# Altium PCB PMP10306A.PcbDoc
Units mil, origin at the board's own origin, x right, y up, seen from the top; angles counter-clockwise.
Board outline 4950 x 3450 mil, 2 copper layers (Top Layer, Bottom Layer), stack 62 mil thick; 21 components, 0 nets, 12 pads, 0 vias.
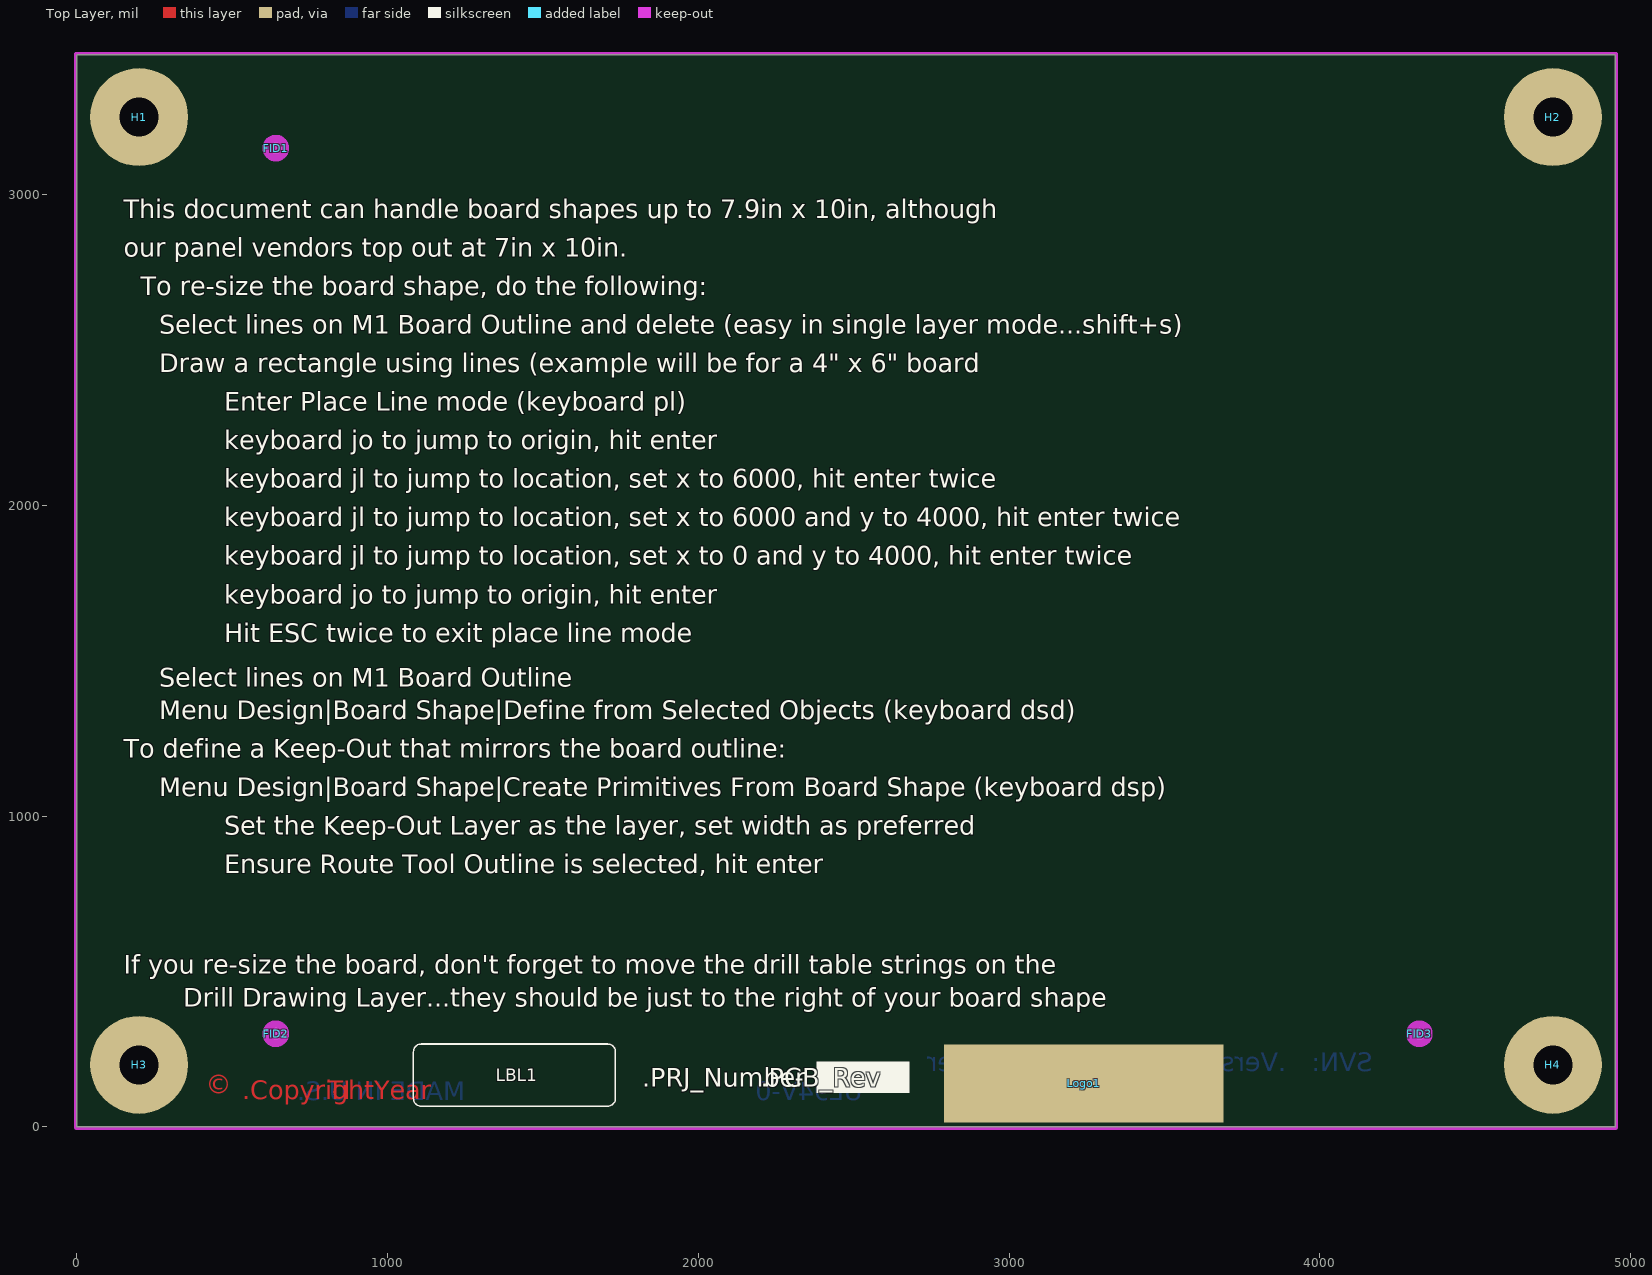
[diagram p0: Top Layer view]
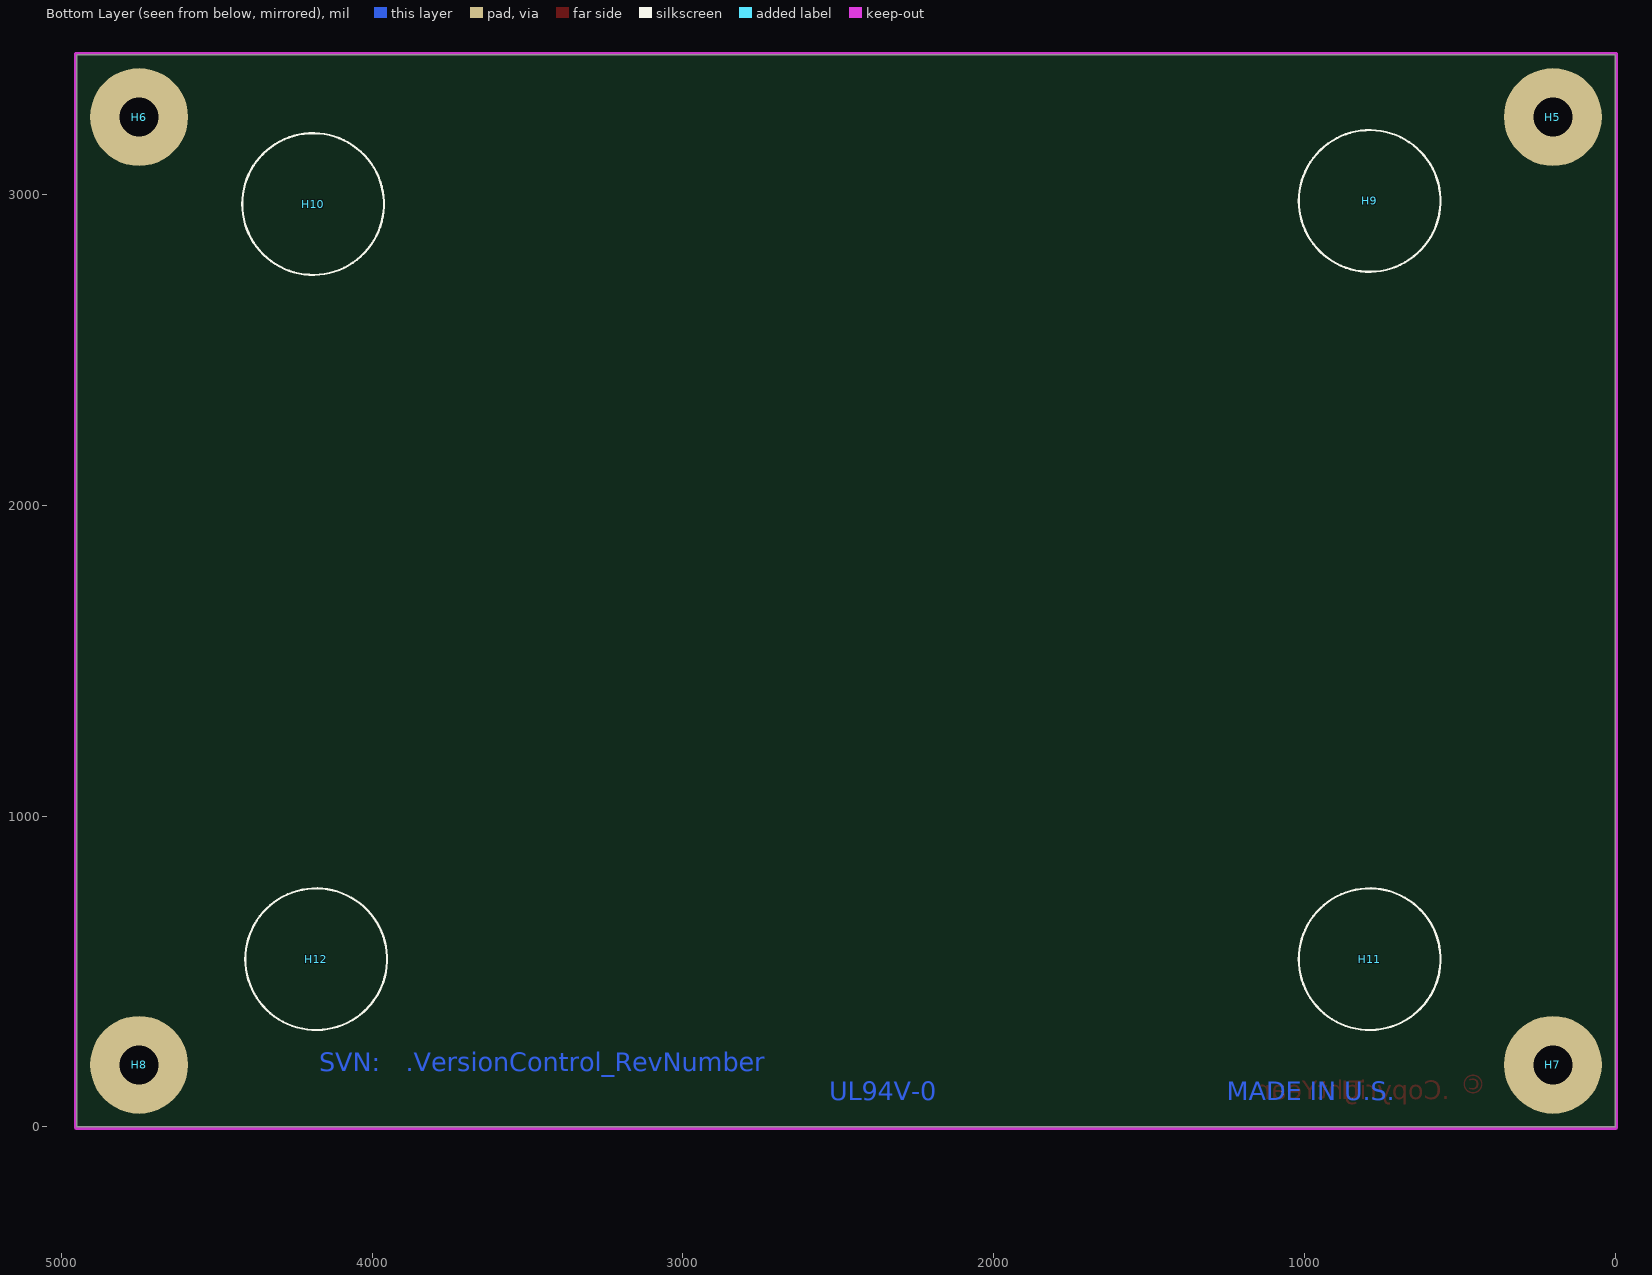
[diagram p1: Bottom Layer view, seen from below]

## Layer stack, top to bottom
Top Layer: signal copper 1.4
Dielectric: core 59.2, FR-4, Dk 4.8
Bottom Layer: signal copper 1.4

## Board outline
0,0 4950,0 4950,3450 0,3450

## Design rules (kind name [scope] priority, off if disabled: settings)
AcuteAngle [All] p1: minimum=4.50000000000000E+0001 checktracksonly=FALSE
AssemblyTestPointUsage [All] p1: valid=2
Clearance Clearance_BoardEdge_MountingHoles [OnCopper and InComponentClass('Mounting Holes') vs IsKeepOut] p1: gap=40
Clearance Clearance_BoardEdge_Poly [OnCopper and InPoly vs IsKeepOut] p2: gap=25
Clearance Clearance_BoardEdge [OnCopper and Not InComponentClass('Logo') and not InComponentClass('FiducialMark') and not InRegion(1000,500,4000,800) and Not IsKeepout vs IsKeepOut] p3: gap=75
Clearance Clearance_Poly [InPolygon] p4: gap=25
Clearance [All] p5: gap=8
ComponentClearance ComponentClearance_Shunt [InComponentClass('Header') vs InComponentClass('Shunt')] p1: gap=0 collisioncheckmode=3 verticalgap=0 showdistances=FALSE
ComponentClearance ComponentClearance_Logo [InComponentClass('Logo')] p2: gap=50 collisioncheckmode=3 verticalgap=10 showdistances=FALSE
ComponentClearance ComponentClearance_ScrewToNut [(HasFootprint('NY PMS 440 0025 PH')) vs (HasFootprint('Keystone_1902C'))] p3: gap=5 collisioncheckmode=3 verticalgap=10 showdistances=FALSE
ComponentClearance ComponentClearance_MountingHoles [InComponentClass('Mounting Holes')] p4: gap=250 collisioncheckmode=3 verticalgap=100000 showdistances=FALSE
ComponentClearance ComponentClearance_SmallPassives [HasFootprint('0201*') or HasFootprint('0402*') or HasFootprint('0508') or HasFootprint('0603*') or HasFootprint('0612') or HasFootprint('0805*') or HasFootprint('0815*') or HasFootprint('0830*') or HasFootprint('1206*') or HasFootprint('1210*') or HasFootprint('1808*') or HasFootprint('1812*') or HasFootprint('1825*') or HasFootprint('2010*') or HasFootprint('2220*') or HasFootprint('2225*') or HasFootprint('2512*') or HasFootprint('2728*') or HasFootprint('3518*') vs HasFootprint('0201*') or HasFootprint('0402*') or HasFootprint('0508') or HasFootprint('0603*') or HasFootprint('0612') or HasFootprint('0805*') or HasFootprint('0815*') or HasFootprint('0830*') or HasFootprint('1206*') or HasFootprint('1210*') or HasFootprint('1808*') or HasFootprint('1812*') or HasFootprint('1825*') or HasFootprint('2010*') or HasFootprint('2220*') or HasFootprint('2225*') or HasFootprint('2512*') or HasFootprint('2728*') or HasFootprint('3518*')] p5: gap=20 collisioncheckmode=3 verticalgap=10 showdistances=FALSE
ComponentClearance ComponentClearance_THtoSMT [IsThruComponent vs IsSMTComponent] p6: gap=100 collisioncheckmode=3 verticalgap=30 showdistances=FALSE
ComponentClearance ComponentClearance_THtoTH [IsThruComponent vs IsThruComponent] p7: gap=118.11 collisioncheckmode=3 verticalgap=30 showdistances=FALSE
ComponentClearance [All] p8: gap=40 collisioncheckmode=3 verticalgap=10 showdistances=FALSE
DiffPairsRouting [All] p1: maxlimit=100 minlimit=10 mostfreqgap=10 maxuncoupledlength=1000
FabricationTestPointUsage TestPointUsage [All] p1: valid=2 allowmultiple=FALSE
FabricationTestpoint Testpoint [All] p1: side=3 testpointundercomponent=TRUE minsize=40 maxsize=100 preferedsize=60 minholesize=0 maxholesize=40 preferedholesize=32 testpointgrid=1 allowsidetop=TRUE allowsidebottom=TRUE usegrid=TRUE gridtolerance=0.01
FanoutControl Fanout_LCC [IsLCC] p1: bgadir=Out bgaviamode=Centered fanoutstyle=Auto fanoutdirection=Alternating viagrid=1 // Fanout_LCC (Default Rule)
FanoutControl Fanout_BGA [IsBGA] p2: bgadir=Out bgaviamode=Centered fanoutstyle=Auto fanoutdirection=Alternating viagrid=1 // Fanout_BGA (Default Rule)
FanoutControl Fanout_Default [All] p4: bgadir=Out bgaviamode=Centered fanoutstyle=Auto fanoutdirection=Alternating viagrid=1 // Fanout_Default (Default Rule)
FanoutControl Fanout_Small [(CompPinCount < 5)] p5: bgadir=Out bgaviamode=Centered fanoutstyle=Auto fanoutdirection=OutThenIn viagrid=1 // Fanout_Small (Default Rule)
HoleSize [All] p1: absolutevalues=TRUE maxlimit=251 minlimit=8 maxpercent=80.000 minpercent=20.000
MinimumAnnularRing MinimumAnnularRing_ThermalPadVias [IsVia and InAnyComponent] p1: minimumring=5.91
MinimumAnnularRing [All] p2: minimumring=9
MinimumSolderMaskSliver MinimumSolderMaskSliver_Logo [InComponentClass('Logo') vs InComponentClass('Logo')] p1: minsoldermaskwidth=0.7
MinimumSolderMaskSliver [All] p2: minsoldermaskwidth=3.94
PlaneConnect [All] p1: planeconnectstyle=Relief reliefexpansion=10 reliefentries=4 reliefconductorwidth=10 reliefairgap=10
PolygonConnect [All] p1: connectstyle=Relief reliefconductorwidth=10 reliefentries=4 polygonreliefangle="90 Angle" airgapwidth=10
RoutingVias ThermalPadVias [IsVia and InAnyComponent] p1: holewidth=7.87 width=19.68 viastyle="Through Hole" minholewidth=7.87 minwidth=19.68 maxholewidth=12.99 maxwidth=23.62
RoutingVias [All] p2: holewidth=16 width=34 viastyle="Through Hole" minholewidth=7.87 minwidth=26 maxholewidth=40 maxwidth=65
SMDToCorner [All] p1: distance=30000
SilkToSilkClearance [All] p1: silktosilkclearance=5
SilkscreenOverComponentPads [All] p1: minsilkscreentomaskgap=5
SolderMaskExpansion [All] p1: expansion=1.97
Width [All] p1: maxlimit=100 minlimit=6 preferedwidth=10 checkconnectedcopper=TRUE
14 further rules are at their usual default settings.

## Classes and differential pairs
component class "Mounting Holes": H1 H2 H3 H4
component class Logo: Logo1
component class FiducialMark: FID1 FID2 FID3
component class AssemblyNote: ZZ1 ZZ2 ZZ3 ZZ4
component class Label: LBL1

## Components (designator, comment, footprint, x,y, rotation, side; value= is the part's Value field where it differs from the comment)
FID1 "Fiducial" Fiducial10-20 640,3150 r0 top
FID2 "Fiducial" Fiducial10-20 640,300 r0 top
FID3 "Fiducial" Fiducial10-20 4320,300 r0 top
H1 "NY PMS 440 0025 PH" "NY PMS 440 0025 PH" 200,3250 r0 top locked
H2 "NY PMS 440 0025 PH" "NY PMS 440 0025 PH" 4750,3250 r0 top locked
H3 "NY PMS 440 0025 PH" "NY PMS 440 0025 PH" 200,200 r0 top locked
H4 "NY PMS 440 0025 PH" "NY PMS 440 0025 PH" 4750,200 r0 top locked
H5 "1902C" Keystone_1902C 200,3250 r180 bottom locked
H6 "1902C" Keystone_1902C 4750,3250 r180 bottom locked
H7 "1902C" Keystone_1902C 200,200 r180 bottom locked
H8 "1902C" Keystone_1902C 4750,200 r180 bottom locked
H9 "SJ-5303 (CLEAR)" Bumpon_SJ5003Transparent 790,2980 r180 bottom
H10 "SJ-5303 (CLEAR)" Bumpon_SJ5003Transparent 4190,2970 r180 bottom
H11 "SJ-5303 (CLEAR)" Bumpon_SJ5003Transparent 790,540 r180 bottom
H12 "SJ-5303 (CLEAR)" Bumpon_SJ5003Transparent 4180,540 r180 bottom
LBL1 "Size: 0.65\" x 0.20 \"" Label_650x200 1408,167 r0 top
Logo1 "Texas Instruments" TI_Stacked_SolderMask_Small 3240,140 r0 top
ZZ1 "This Assembly Note is for PCB labels only" AssemblyNoteLabel 185,3938 r0 top
ZZ2 "These assemblies are ESD sensitive, ESD precautions shall be observed." AssemblyNote 185,3829.11 r0 top
ZZ3 "These assemblies must be clean and free from flux and all contaminants. Use of no clean flux is not acceptable." AssemblyNote 185,3740.56 r0 top
ZZ4 "These assemblies must comply with workmanship standards IPC-A-610 Class 2, unless otherwise specified." AssemblyNote 185,3652 r0 top

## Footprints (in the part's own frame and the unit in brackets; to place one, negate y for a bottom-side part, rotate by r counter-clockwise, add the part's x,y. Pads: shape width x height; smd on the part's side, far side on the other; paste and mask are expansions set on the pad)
AssemblyNote [mil] "Assembly Note"
AssemblyNoteLabel [mil] "Assembly Note for PCB Labels"
Bumpon_SJ5003Transparent [mil] "3M Hemispherical Bumpon transparent"
  round 1 on Mech4: 0(0,0)
  silkscreen extent -228,-228 228,228, body extent -217,-218 219,218, height 197
Fiducial10-20 [mm]
  round 1 smd paste-0.5 mask+0.5: 1(0,0)
  Top Layer keep-out circle w1.178: c0,0 r0.5
Keystone_1902C [mil] "Hex Standoff, 4-40 threaded, nylon"
  body extent -145,-126 146,126, height 501
Label_650x200 [mil] "Thermal Transfer Label"
  silkscreen extent -325,-100 325,100, body extent -326,-101 326,101, height 1
"NY PMS 440 0025 PH" [mm] "4-40 nylon screw and mounting hole"
  round 8 hole 3.2: 1(0,0)
  body extent -3.3,-3.3 3.3,3.3, height 2.69
TI_Stacked_SolderMask_Small [mil]
  rect 900x250 smd paste-125 mask-125: 0(0,0)

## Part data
FID1 FID2 FID3: "Fiducial mark.  There is nothing to buy or mount."
H1 H2 H3 H4: "Machine Screw, Round, #4-40 x 1/4, Nylon, Philips panhead"
H5 H6 H7 H8: "Standoff, Hex, 0.5\"L #4-40 Nylon"
H9 H10 H11 H12: "Bumpon, Hemisphere, 0.44 X 0.20, Clear"
LBL1: library part THT-14-423-10, "Thermal Transfer Printable Labels, 0.650\" W x 0.200\" H - 10,000 per roll"
Logo1: library part TI_Logo, "Texas Instrument Corporate Signature"
ZZ1: library part AssemblyNoteLabel
ZZ2 ZZ3 ZZ4: library part AssemblyNote

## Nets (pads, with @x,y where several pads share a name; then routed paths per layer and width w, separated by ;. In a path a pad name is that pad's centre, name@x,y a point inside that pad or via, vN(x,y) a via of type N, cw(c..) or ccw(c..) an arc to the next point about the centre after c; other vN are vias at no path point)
pads on no net: FID1.1 FID2.1 FID3.1 H1.1 H2.1 H3.1 H4.1 H9.0 H10.0 H11.0 H12.0 Logo1.0

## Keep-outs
Keep-Out Layer:
  lines w10: -5,0 ccw(c0,0) 0,-5 ; -5,0 ccw(c0,0) 0,-5 ; -5,0 ccw(c0,0) 0,-5 ; -5,0 ccw(c0,0) 0,-5 ; -5,0 ccw(c0,0) 0,-5 ; -5,0 ccw(c0,0) 0,-5 ; -5,0 -5,3450 ; -5,3450 cw(c0,3450) 0,3455 ; -5,3450 cw(c0,3450) 0,3455 ; -5,3450 cw(c0,3450) 0,3455 ; -5,3450 cw(c0,3450) 0,3455 ; -5,3450 cw(c0,3450) 0,3455 ; -5,3450 cw(c0,3450) 0,3455 ; 0,-5 4950,-5 ; 0,3455 4950,3455 ; 4950,-5 ccw(c4950,0) 4955,0 ; 4950,-5 ccw(c4950,0) 4955,0 ; 4950,-5 ccw(c4950,0) 4955,0 ; 4950,-5 ccw(c4950,0) 4955,0 ; 4950,-5 ccw(c4950,0) 4955,0 ; 4950,-5 ccw(c4950,0) 4955,0 ; 4950,3455 cw(c4950,3450) 4955,3450 ; 4950,3455 cw(c4950,3450) 4955,3450 ; 4950,3455 cw(c4950,3450) 4955,3450 ; 4950,3455 cw(c4950,3450) 4955,3450 ; 4950,3455 cw(c4950,3450) 4955,3450 ; 4950,3455 cw(c4950,3450) 4955,3450 ; 4955,0 4955,3450
  text ".Layer_Name" at 577,-858.49 h60

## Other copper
Top Layer:
  text ".CopyrightYear" at 532,90 h60
  text "TI" at 808,90 h60
  text "©" at 415,86.48 h105
  text ".Layer_Name" at 577,-858.49 h60
Bottom Layer:
  text ".VersionControl_RevNumber" at 3891,179.5 h60
  text "SVN:" at 4170,179.5 h60
  text "MADE IN U.S." at 1250,86.5 h60
  text "UL94V-0" at 2529.5,86.5 h60
  text ".Layer_Name" at 577,-858.49 h60

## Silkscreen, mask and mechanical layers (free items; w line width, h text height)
Top Overlay:
  region: 2680,210 2380,210 2380,110 2680,110
  text "This document can handle board shapes up to 7.9in x 10in, although" at 150,2925 h60
  text "our panel vendors top out at 7in x 10in." at 150,2800.94 h60
  text "To re-size the board shape, do the following:" at 205,2676.88 h60
  text "Select lines on M1 Board Outline and delete (easy in single layer mode...shift+s)" at 265,2552.82 h60
  text "Draw a rectangle using lines (example will be for a 4\" x 6\" board" at 265,2428.76 h60
  text "Enter Place Line mode (keyboard pl)" at 475,2304.71 h60
  text "keyboard jo to jump to origin, hit enter" at 475,2180.65 h60
  text "keyboard jl to jump to location, set x to 6000, hit enter twice" at 475,2056.59 h60
  text "keyboard jl to jump to location, set x to 6000 and y to 4000, hit enter twice" at 475,1932.53 h60
  text "keyboard jl to jump to location, set x to 0 and y to 4000, hit enter twice" at 475,1808.47 h60
  text "keyboard jo to jump to origin, hit enter" at 475,1684.41 h60
  text "Hit ESC twice to exit place line mode" at 475,1560.35 h60
  text "Select lines on M1 Board Outline" at 265,1416.3 h60
  text "Menu Design|Board Shape|Define from Selected Objects (keyboard dsd)" at 265,1312.24 h60
  text "To define a Keep-Out that mirrors the board outline:" at 150,1188.18 h60
  text "Menu Design|Board Shape|Create Primitives From Board Shape (keyboard dsp)" at 265,1064.12 h60
  text "Set the Keep-Out Layer as the layer, set width as preferred" at 475,940.06 h60
  text "Ensure Route Tool Outline is selected, hit enter" at 475,816 h60
  text "If you re-size the board, don't forget to move the drill table strings on the" at 150,493 h60
  text "Drill Drawing Layer...they should be just to the right of your board shape" at 343,387 h60
  text ".PRJ_Number" at 1820,130.01 h60
  text ".PCB_Rev" at 2200,130.01 h60
  text "-" at 2310,130.01 h60
  text ".Layer_Name" at 577,-858.49 h60
Bottom Overlay:
  text ".Layer_Name" at 577,-858.49 h60
Top Paste:
  text ".Layer_Name" at 577,-858.49 h60
Bottom Paste:
  text ".Layer_Name" at 577,-858.49 h60
Top Solder:
  text ".Layer_Name" at 577,-858.49 h60
  text ".Layer_Name" at 577,-858.49 h60
Bottom Solder:
  text ".Layer_Name" at 577,-858.49 h60
Drill Guide:
  text ".Layer_Name" at 577,-858.49 h60
M1 Board Outline:
  the board outline again, w10
  text ".Layer_Name" at 577,-858.49 h60
M2 Board Dimensions:
  rectangle: -0.5,-285.5 124.5,-160.5
  rectangle: 124.5,-410.5 499.5,-285.5
  lines w7: -0.5,-285.5 999.5,-285.5 ; 124.5,-410.5 124.5,-160.5 ; 249.5,-410.5 249.5,-160.5 ; 499.5,-410.5 499.5,-160.5 ; 749.5,-410.5 749.5,-160.5 ; -0.5,-410.5 999.5,-410.5 999.5,-160.5 -0.5,-160.5 -0.5,-410.5
  lines w10: -0.5,-475.5 -0.5,-455.5 ; 59.5,-485.5 -0.5,-465.5 ; 59.5,-445.5 -0.5,-465.5 ; 223.58,-465.5 -0.5,-465.5 ; 775.42,-465.5 999.5,-465.5 ; 939.5,-485.5 999.5,-465.5 ; 939.5,-445.5 999.5,-465.5 ; 999.5,-475.5 999.5,-455.5
  text "1000 (mil)" at 233.58,-501.49 h60
  text ".Layer_Name" at 577,-858.49 h60
M3 3D STEP Top:
  text ".Layer_Name" at 577,-858.49 h60
M4 3D STEP Bottom:
  text ".Layer_Name" at 577,-858.49 h60
M5 Assembly Top:
  lines w10: -292,-930.17 6308,-930.17 ; -292,-726.83 6310,-726.83 ; -292,-523.5 -292,-1133.5 3713,-1133.5 6310,-1133.5 6310,-523.5 -291.5,-523.5 -291.5,-1133.5 1284,-1133.5 ; 2173,-1133.5 2173,-523.5 ; 3440,-726.83 3440,-523.5 ; 4280,-726.83 4280,-523.5 ; 4902,-1140 4902,-937.17
  text "COMPONENTS MARKED 'DNP' SHOULD NOT BE POPULATED." at 1153.5,-318.5 h60
  text "ASSEMBLY VARIANT:" at 1153,-434 h60
  text ".VariantName" at 2189,-434 h60
  text "PCB VIEWED FROM TOP SIDE" at -228.5,-655.67 h60
  text "BOARD #:" at 2248,-655.67 h60
  text ".PRJ_Number" at 2793.5,-655.67 h60
  text "REV:" at 3638,-655.67 h60
  text ".PCB_Rev" at 3929.5,-655.67 h60
  text "SVN REV:" at 4476,-655.67 h60
  text ".VersionControl_RevNumber" at 4982,-655.67 h60
  text "IGNORE ->" at -228.5,-858.49 h60
  text "PLOT NAME =" at -228.5,-1064.34 h60
  text ".plot_File_Name" at 577,-1064.34 h60
  text "GENERATED    :" at 2250,-1064.34 h60
  text ".Print_Date" at 3119.5,-1064.34 h60
  text ".Print_Time" at 3848.5,-1064.34 h60
  text "TEXAS INSTRUMENTS" at 5113,-1064.34 h60
M6 Assembly Bottom:
  lines w10: -292.5,-727.33 6309.5,-727.33 ; -290.5,-930.67 6309.5,-930.67 ; 1115.5,-1140.5 1115.5,-937.67 ; 1737.5,-727.33 1737.5,-524 ; 2577.5,-727.33 2577.5,-524 ; 3844.5,-1134 3844.5,-524 ; 4733.5,-1134 6309,-1134 6309,-524 -292.5,-524 -292.5,-1134 2304.5,-1134 6309.5,-1134 6309.5,-524
  text "COMPONENTS MARKED 'DNP' SHOULD NOT BE POPULATED." at 6102,-318 h60
  text ".VariantName" at 5058,-434 h60
  text "ASSEMBLY VARIANT:" at 6097,-434 h60
  text ".VersionControl_RevNumber" at 1035.5,-656.17 h60
  text "SVN REV:" at 1541.5,-656.17 h60
  text ".PCB_Rev" at 2088,-656.17 h60
  text "REV:" at 2379.5,-656.17 h60
  text ".PRJ_Number" at 3224,-656.17 h60
  text "BOARD #:" at 3769.5,-656.17 h60
  text "PCB VIEWED FROM BOTTOM SIDE" at 6246,-656.17 h60
  text "IGNORE ->" at 2547.85,-858.49 h60
  text "TEXAS INSTRUMENTS" at 904.5,-1064.84 h60
  text ".Print_Time" at 2169,-1064.84 h60
  text ".Print_Date" at 2898,-1064.84 h60
  text "GENERATED    :" at 3767.5,-1064.84 h60
  text ".plot_File_Name" at 5440.5,-1064.84 h60
  text "PLOT NAME =" at 6246,-1064.84 h60
M9 Title Sheet:
  drawing of 57 lines, arcs and shapes, not listed
  text "1" at 739.84,8036.5 h70
  text "2" at 3235.5,8036.5 h70
  text "3" at 5724.84,8036.5 h70
  text "4" at 8231.51,8036.5 h70
  text "5" at 10730.5,8036.5 h70
  text "6" at 13235.5,8036.5 h70
  text "A" at -416.5,6893.5 h70
  text "A" at 14383.5,6893.5 h70
  text "B" at -416.5,4513.5 h70
  text "B" at 14383.5,4513.5 h70
  text "C" at -416.5,2138.5 h70
  text "C" at 14383.5,2138.5 h70
  text "PROJECT TITLE:" at 11343.5,277.5 h45
  text ".PRJ_Title" at 11393.5,144.17 h70
  text "DESIGNED FOR:" at 11343.5,-23.5 h45
  text ".PRJ_Customer" at 11393.5,-163.5 h70
  text "D" at -416.5,-231.5 h70
  text "D" at 14383.5,-231.5 h70
  text "FILE NAME:" at 11343.5,-323.5 h45
  text ".PCB_File_Name_No_Path" at 11393.5,-443.5 h70
  text "Texas Instruments (TI) and/or its licensors do not warrant the accuracy or completeness of this specification" at 6374,-605.34 h45
  text "ENGINEER:" at 11343.5,-613.5 h45
  text "LAYOUT BY:" at 12848.5,-613.5 h45
  text "or any information contained therein. TI and/or its licensors do not warrant that this design will meet" at 6329.01,-718 h45
  text ".PRJ_Engineer" at 11393.5,-768.49 h70
  text ".PCB_Layout" at 12899,-768.49 h70
  text "the specifications, will be suitable for your application or fit for any particular purpose, or will operate in" at 6329.01,-830.67 h45
  text ".Layer_Name" at 577,-858.49 h60
  text "ALTIUM DESIGNER VERSION:" at 12848.5,-923.5 h45
  text "an implementation. TI and/or its licensors do not warrant that the design is production worthy. You should" at 6329.01,-943.33 h45
  text "completely validate and test your design implementation to confirm the system functionality for your application." at 6374,-1056 h45
  text ".print_Scale" at 11393.5,-1056.83 h70
  text ".Application_BuildNumber" at 12899,-1056.83 h70
  text "1" at 739.84,-1263.5 h70
  text "2" at 3235.5,-1263.5 h70
  text "3" at 5724.84,-1263.5 h70
  text "4" at 8231.51,-1263.5 h70
  text "5" at 10730.5,-1263.5 h70
  text "6" at 13235.5,-1263.5 h70
M10 Fab Notes:
  drawing of 212 lines, arcs and shapes, not listed
  text "DESIGN INFORMATION" at 12381.02,6810 h60
  text "(REFER ALSO ARRAY/PANEL PROFILING INFORMATION)" at 12019.46,6648.29 h60
  text "BOARD SIZE" at 11333.46,6644 h60
  text "3450MIL" at 11795.78,6516.18 h60
  text "X" at 12301.46,6516.18 h60
  text "4950MIL" at 12532.78,6516.18 h60
  text "Number of Layers :" at 11736.46,6319 h60
  text "2" at 12831.27,6309 h60
  text "MIN. TRACK WIDTH:" at 11736.46,6180 h60
  text "8" at 12832.7,6180 h60
  text "MIL" at 12987.46,6180 h60
  text "MIN. CLEARANCE:" at 11736.46,6048 h60
  text "8" at 12832.7,6048 h60
  text "MIL" at 12987.46,6048 h60
  text "MIN. VIA PAD SIZE:" at 11736.46,5916 h60
  text "24" at 12802.71,5916 h60
  text "MIL" at 12987.46,5916 h60
  text "0.05mm (2MIL)" at 12431.46,5774.29 h60
  text "MINIMUM ANNULAR RING" at 11407.23,5770 h60
  text "EXTERNAL" at 13139.46,5770 h60
  text "PER" at 11607.23,5652 h60
  text "IPC-D-275 CLASS 2 LEVEL C" at 11827.23,5652 h60
  text "MIL, HOLES" at 13315.46,5539.71 h60
  text "+/-" at 12923,5539 h60
  text "+/-" at 13777,5539 h60
  text "REGISTRATION TOLERANCES:" at 11407.23,5534 h60
  text "METAL" at 12607,5534 h60
  text "5" at 13183.2,5534 h60
  text "3" at 14016.2,5534 h60
  text "MIL" at 14132.46,5534 h60
  text "MATERIAL:" at 11332.46,5324.54 h60
  text "FR-4 High Tg" at 12318.9,5184.21 h60
  text "FR-408" at 11753.46,5175.64 h60
  text "X" at 12165.46,5175.64 h60
  text "OTHER" at 13241.46,5175.64 h60
  text "62 MIL (1.6mm) +/-10%" at 12073.56,5012.92 h60
  text "THICKNESS:" at 11407.23,5008.64 h60
  text "X" at 11945.4,5008.64 h60
  text "OTHER" at 13358.46,5008.64 h60
  text "TOLERANCE:" at 11407.23,4850.64 h60
  text "X" at 12246.53,4850.64 h60
  text "ANSI IPC-6012 TYPE 3 CLASS 2" at 12433.48,4850.64 h60
  text "OTHER +/-" at 12433.46,4694.64 h60
  text "BOW & TWIST:" at 11407.23,4537.64 h60
  text "X" at 12246.53,4537.64 h60
  text "ANSI IPC-6012 TYPE 3 CLASS 2" at 12433.48,4537.64 h60
  text "OTHER +/-" at 12433.46,4379.13 h60
  text "COPPER THICKNESS (FINISHED):" at 11332.46,4243.64 h60
  text "1.4MIL (1oz)" at 12212.46,4090.92 h60
  text "2MIL (1.4oz)" at 12979.46,4090.92 h60
  text "2.8MIL (2oz)" at 13706.46,4090.92 h60
  text "OUTER:" at 11689.46,4086.64 h60
  text "X" at 12084,4086 h60
  text "1.4MIL (1oz)" at 12212.46,3933.92 h60
  text "2.8MIL (2oz)" at 12979.46,3933.92 h60
  text "N/A" at 13706,3934.29 h60
  text "INNER SIGNAL:" at 11400.38,3929.64 h60
  text "X" at 12085.42,3929.64 h60
  text "DRILLING:" at 11332.46,3790.64 h60
  text "REFERENCE:" at 11407.23,3673.64 h60
  text "X" at 12055.46,3673.64 h60
  text "AS SHOWN" at 12242.46,3673.64 h60
  text "X" at 12956.46,3673.64 h60
  text "NC_DRILL FILES" at 13093.46,3673.64 h60
  text "PTH MIN COPPER THICKNESS:" at 11407.23,3515.64 h60
  text "X" at 12757.46,3515.64 h60
  text "1MIL" at 12894.46,3515.64 h60
  text "OTHER" at 13391.46,3515.64 h60
  text "BOARD FINISH:" at 11332.46,3356.64 h60
  text "SILKSCREEN:" at 11487.68,3238.64 h60
  text "X" at 12436.46,3238.64 h60
  text "TOP" at 12562.46,3238.64 h60
  text "X" at 12946.46,3238.64 h60
  text "BOTTOM" at 13073.46,3238.64 h60
  text "SILKSCREEN COLOR:" at 11487.68,3071.64 h60
  text "X" at 12435.42,3071.64 h60
  text "WHITE" at 12562.46,3071.64 h60
  text "OTHER" at 13073.46,3071.64 h60
  text "SOLDER RESIST COLOR:" at 11487.68,2901.64 h60
  text "X" at 12055.42,2742.44 h60
  text "GREEN" at 12182.46,2742.44 h60
  text "BLUE" at 12773.46,2742.44 h60
  text "OTHER" at 13311.46,2742.44 h60
  text "IMMERSION GOLD (ENIG)" at 12393.46,2553.92 h60
  text "ENEPIG" at 13731,2550.64 h60
  text "SURFACE FINISH:" at 11332.46,2549.64 h60
  text "X" at 12206.51,2549.64 h60
  text "IMM. TIN/SILVER OR EQUIV" at 11662,2392.64 h60
  text "OTHER" at 13093.46,2392.64 h60
  text "ARRAY/PANEL:" at 11332.46,2213.64 h60
  text "CUT AND TRIM PER MECH LAYER 1" at 12393.46,2209.35 h60
  text "N.C. ROUTE" at 12393.46,2057.64 h60
  text "X" at 13072.46,2057.64 h60
  text "V. SCORE" at 13259.46,2057.64 h60
  text "CERTIFICATION:" at 11332.46,1920.64 h60
  text "MATERIALS AND WORKMANSHIP FOR ALL PCBS" at 12057.46,1920.64 h60
  text "TO MEET OR EXCEED THE REQUIREMENTS OF:" at 12057.46,1822.64 h60
  text "X" at 11683.96,1686.13 h60
  text "ANSI IPC-A-600F CLASS ->" at 11822.96,1686.13 h60
  text "X" at 13462.02,1686.13 h60
  text "2" at 13580.96,1686.14 h60
  text "1" at 13265.96,1684.64 h60
  text "3" at 13934.96,1684.64 h60
  text "X" at 11686.02,1526.64 h60
  text "UL 94V-0" at 11822.96,1526.64 h60
  text "X" at 12498.02,1526.64 h60
  text "RoHS" at 12634.96,1526.64 h60
  text "OTHER" at 13279.36,1526.64 h60
  text "PER ORDER" at 13676.42,1526.64 h60
  text "ADDITIONAL REQUIREMENTS:" at 11332.46,1385.64 h60
  text "MICROSECTION:" at 11407.23,1270.64 h60
  text "YES" at 12312.96,1270.64 h60
  text "REQUIRED" at 13174.46,1114.49 h60
  text "BARE BOARD ELEC. TEST:" at 11407.23,1111.64 h60
  text "NONE" at 12712.96,1111.64 h60
  text "X" at 13047.46,1111.64 h60
  text "PER ORDER" at 13766.46,1111.64 h60
  text "MANUFACTURER'S UL:" at 11407.23,954.64 h60
  text "RAIL" at 12572.96,950.35 h60
  text "METAL" at 13064.77,950.35 h60
  text "X" at 13440,950 h60
  text "SILK" at 13576.46,950.35 h60
  text ".Layer_Name" at 577,-858.49 h60
M11 Gerber Information:
  lines w10: -292,-930.17 6308,-930.17 ; -292,-726.83 6310,-726.83 ; -292,-523.5 -292,-1133.5 3713,-1133.5 6310,-1133.5 6310,-523.5 -291.5,-523.5 -291.5,-1133.5 1284,-1133.5 ; 2173,-1133.5 2173,-523.5 ; 3440,-726.83 3440,-523.5 ; 4280,-726.83 4280,-523.5 ; 4902,-1140 4902,-937.17
  text "ALL ARTWORK VIEWED FROM TOP SIDE" at -228.5,-655.67 h60
  text "BOARD #:" at 2248,-655.67 h60
  text ".PRJ_Number" at 2793.5,-655.67 h60
  text "REV:" at 3638,-655.67 h60
  text ".PCB_Rev" at 3929.5,-655.67 h60
  text "SVN REV:" at 4476,-655.67 h60
  text ".VersionControl_RevNumber" at 4982,-655.67 h60
  text "LAYER NAME =" at -228.5,-858.49 h60
  text "PLOT NAME =" at -228.5,-1064.34 h60
  text ".plot_File_Name" at 577,-1064.34 h60
  text "GENERATED    :" at 2250,-1064.34 h60
  text ".Print_Date" at 3119.5,-1064.34 h60
  text ".Print_Time" at 3848.5,-1064.34 h60
  text "TEXAS INSTRUMENTS" at 5113,-1064.34 h60
M12 Stackup:
  lines w6: 11360,7460 13910,7460 ; 11360,7564.4 13910,7564.4 ; 11300,6975 ccw(c11334,6975) 11334,6941 13936,6941 ccw(c13936,6975) 13970,6975 13970,7681 ccw(c13936,7681) 13936,7715 11334,7715 ccw(c11334,7681) 11300,7681 11300,6975
  text "The Stackup Legend below this is static." at 11605.5,7874.5 h60
  text "If you change the stackup, update the Legend." at 11615.5,7784.5 h60
  text "Layer Stack Up Detail for: Ref_Design.PcbDoc" at 11360,7597.1 h57
  text "Layer" at 11360,7525.4 h24
  text "Gerber" at 12255.81,7525.4 h24
  text "Copper" at 12819.33,7525.4 h24
  text "Dielectric" at 13422.04,7525.4 h24
  text "Name" at 11360,7477.4 h24
  text "Document" at 12255.81,7477.4 h24
  text "Thickness" at 12819.33,7477.4 h24
  text "Material" at 13422.04,7477.4 h24
  text "Top Solder Mask" at 11360,7384.44 h34
  text "(.GTS)" at 12255.81,7384.44 h34
  text "Solder Resist" at 13422.04,7384.44 h34
  text "Top Layer" at 11360,7287.69 h34
  text "(.GTL)" at 12255.81,7287.69 h34
  text "1.4mil" at 12819.33,7287.69 h34
  text "FR-4" at 13422.04,7239.31 h34
  text "Bottom Layer" at 11360,7190.94 h34
  text "(.GBL)" at 12255.81,7190.94 h34
  text "1.4mil" at 12819.33,7190.94 h34
  text "Bottom Solder Mask" at 11360,7094.19 h34
  text "(.GBS)" at 12255.81,7094.19 h34
  text "Solder Resist" at 13422.04,7094.19 h34
  text ".Layer_Name" at 577,-858.49 h60
M13 Component Bodies Top:
  text ".Layer_Name" at 577,-858.49 h60
M14 Component Bodies Bottom:
  text ".Layer_Name" at 577,-858.49 h60
M15 Courtyards Top:
  text ".Layer_Name" at 577,-858.49 h60
M16 Courtyards Bottom:
  text ".Layer_Name" at 577,-858.49 h60
Drill Drawing:
  text ".legend" at 5122.5,725.5 h60
  text "Drill Table" at 5147.5,540.5 h60
  text ".Layer_Name" at 577,-858.49 h60

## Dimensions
0,0 to 0,3450 on M2 Board Dimensions
0,0 to 4950,0 on M2 Board Dimensions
